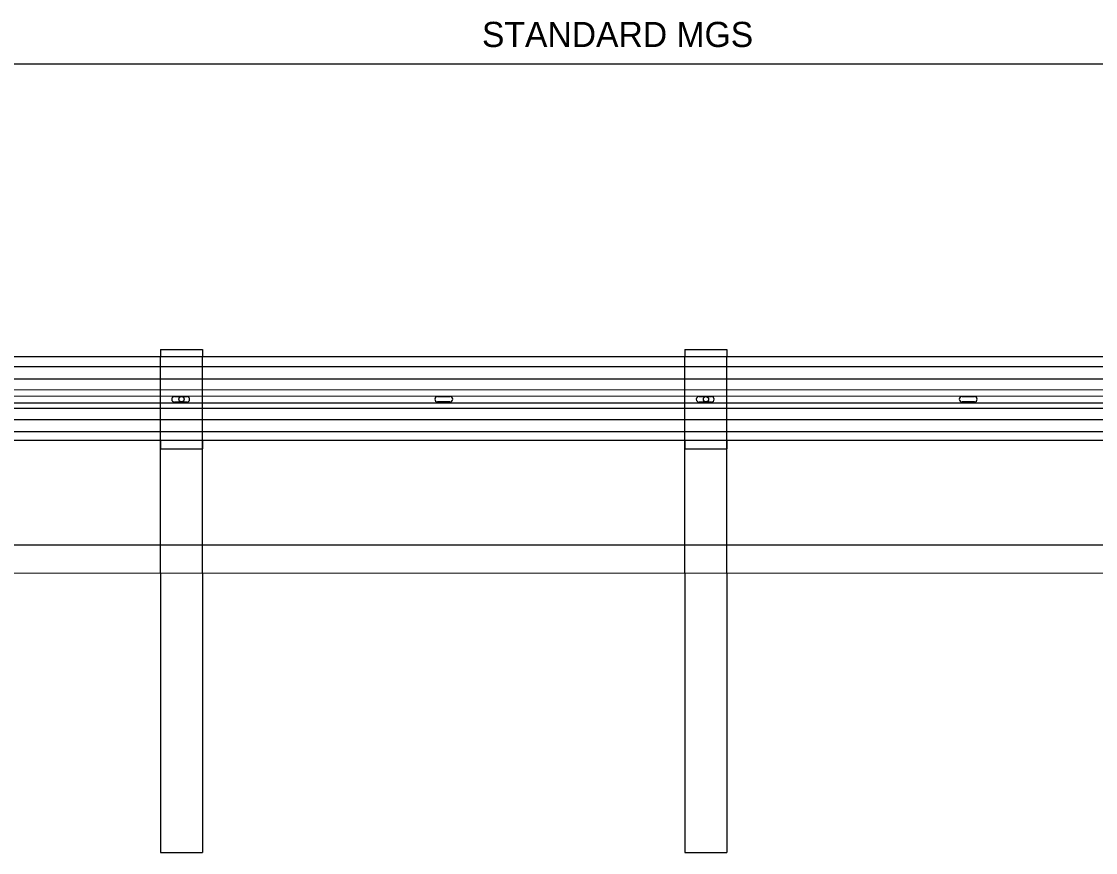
# Model space of a CAD drawing. Extents: x 49991 to 50160, y 49948 to 50051.
# Drawn here: x 50008.44 to 50011, y 49994.318 to 49996.3 of the extents above; entities that cross this region are included whole.
import ezdxf

# ---------------------------------------------------------------- set-up
doc = ezdxf.new("R2010")
doc.units = 0
for name, color, linetype in [('Level 1', 7, 'Continuous'), ('Level 2', 7, 'Continuous'), ('Level 3', 7, 'Continuous'), ('Level 4', 7, 'Continuous')]:
    doc.layers.add(name, color=color, linetype=linetype)

msp = doc.modelspace()

# ---------------------------------------------------------------- linework, layer by layer
at = {"layer": 'Level 1'}
for p, q in [((50008.7716, 49995.5183), (50008.7716, 49995.5019)), ((50008.7716, 49995.5183), (50008.8716, 49995.5183)), ((50008.7716, 49995.5183), (50008.7716, 49995.5016)), ((50008.7716, 49995.5183), (50008.8716, 49995.5183)), ((50008.8716, 49995.5183), (50008.8716, 49995.5016)), ((50008.8716, 49995.5183), (50008.8716, 49995.5017)), ((50010.0216, 49995.5182), (50010.0216, 49995.5015)), ((50010.0216, 49995.5182), (50010.1216, 49995.5182)), ((50010.0216, 49995.5182), (50010.0216, 49995.5015)), ((50010.0216, 49995.5182), (50010.1216, 49995.5182)), ((50010.1216, 49995.5182), (50010.1216, 49995.5019)), ((50010.1216, 49995.5182), (50010.1216, 49995.5016)), ((50004.3866, 49995.5019), (50011.6716, 49995.5014)), ((50004.5497, 49995.4776), (50011.6716, 49995.4776)), ((50004.5497, 49995.4485), (50011.6716, 49995.4479)), ((50004.5497, 49995.4214), (50011.6716, 49995.4224)), ((50005.0854, 49995.4089), (50011.6716, 49995.4067)), ((50011.6716, 49995.3901), (50005.5897, 49995.3902)), ((50008.805, 49995.4058), (50008.8345, 49995.4058)), ((50008.8345, 49995.3927), (50008.805, 49995.3927)), ((50009.4319, 49995.4059), (50009.4614, 49995.4059)), ((50009.4614, 49995.3928), (50009.4319, 49995.3928)), ((50010.055, 49995.4057), (50010.0845, 49995.4057)), ((50010.0845, 49995.3926), (50010.055, 49995.3926)), ((50010.6819, 49995.4059), (50010.7114, 49995.4059)), ((50010.7114, 49995.3928), (50010.6819, 49995.3928)), ((50011.6716, 49995.3772), (50005.5897, 49995.3772)), ((50011.6716, 49995.3503), (50005.5897, 49995.3503)), ((50011.6716, 49995.3213), (50005.5897, 49995.3213)), ((50011.6716, 49995.3011), (50005.5897, 49995.3011)), ((50008.7716, 49995.0515), (50008.7716, 49995.3011)), ((50008.7716, 49995.3009), (50008.7716, 49995.2808)), ((50008.7716, 49995.2808), (50008.8716, 49995.2808)), ((50008.8716, 49995.0515), (50008.8716, 49995.3011)), ((50008.8716, 49995.3009), (50008.8716, 49995.2808)), ((50010.0216, 49995.0515), (50010.0216, 49995.3011)), ((50010.0216, 49995.3009), (50010.0216, 49995.2807)), ((50010.0216, 49995.2807), (50010.1216, 49995.2807)), ((50010.1216, 49995.0515), (50010.1216, 49995.3011)), ((50010.1216, 49995.3009), (50010.1216, 49995.2807)), ((50011.6716, 49995.0514), (50000.8008, 49995.0519)), ((49999.8072, 49994.9853), (50011.6716, 49994.9848))]:
    msp.add_line(p, q, dxfattribs=at)
for centre in [(50008.8216, 49995.3995), (50010.0716, 49995.3994)]:
    msp.add_circle(centre, 0.00625, dxfattribs=at)
for centre, start, end in [((50008.805, 49995.3992), 90, 270), ((50008.8345, 49995.3992), 270, 90), ((50009.4319, 49995.3994), 90, 270), ((50009.4614, 49995.3994), 270, 90), ((50010.055, 49995.3991), 90, 270), ((50010.0845, 49995.3991), 270, 90), ((50010.6819, 49995.3994), 90, 270), ((50010.7114, 49995.3994), 270, 90)]:
    msp.add_arc(centre, 0.00656, start, end, dxfattribs=at)
at = {"layer": 'Level 3'}
msp.add_line((50008.1966, 49996.1994), (50011.5729, 49996.1994), dxfattribs=at)
at = {"layer": 'Level 4'}
for p, q in [((50008.7716, 49995.3011), (50008.7716, 49995.5019)), ((50008.7716, 49995.3009), (50008.7716, 49995.5016)), ((50008.8716, 49995.3011), (50008.8716, 49995.5019)), ((50008.8716, 49995.3009), (50008.8716, 49995.5017)), ((50010.0216, 49995.3011), (50010.0216, 49995.5019)), ((50010.0216, 49995.3009), (50010.0216, 49995.5015)), ((50010.1216, 49995.3011), (50010.1216, 49995.5019)), ((50010.1216, 49995.3009), (50010.1216, 49995.5016)), ((50008.7716, 49994.9849), (50008.7716, 49995.0515)), ((50008.8716, 49994.9849), (50008.8716, 49995.0515)), ((50010.0216, 49994.9848), (50010.0216, 49995.0515)), ((50010.1216, 49994.9848), (50010.1216, 49995.0515)), ((50008.7716, 49994.9849), (50008.7716, 49994.3183)), ((50008.8716, 49994.9849), (50008.8716, 49994.3183)), ((50010.0216, 49994.9849), (50010.0216, 49994.3182)), ((50010.1216, 49994.9849), (50010.1216, 49994.3182)), ((50008.7716, 49994.3183), (50008.8716, 49994.3183)), ((50010.0216, 49994.3182), (50010.1216, 49994.3182))]:
    msp.add_line(p, q, dxfattribs=at)

# ---------------------------------------------------------------- texts
at = {"layer": 'Level 2'}
msp.add_text('STANDARD MGS', height=0.06, dxfattribs=at).set_placement((50009.5377, 49996.2394))

doc.saveas('drawing.dxf')
